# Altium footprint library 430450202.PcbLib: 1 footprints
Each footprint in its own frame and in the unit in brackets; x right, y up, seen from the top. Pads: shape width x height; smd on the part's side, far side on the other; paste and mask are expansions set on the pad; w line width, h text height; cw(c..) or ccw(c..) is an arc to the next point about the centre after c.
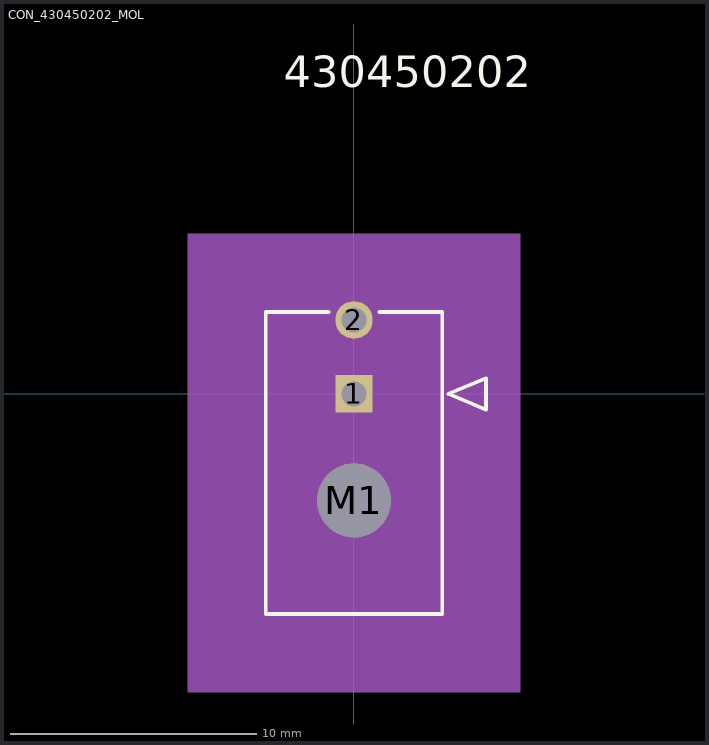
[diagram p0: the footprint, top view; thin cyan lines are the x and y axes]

## CON_430450202_MOL [mm]
pads (3):
  rect 1.52x1.52 hole 1.02 mask+0.076: 1(0,0)
  round 1.52 hole 1.02 mask+0.076: 2(0,3)
  round 3 hole 3 unplated mask+0.076: M1(0,-4.32)
Top Overlay:
  lines w0.152: -1.032,3.32 -3.575,3.32 -3.575,-8.92 3.575,-8.92 3.575,3.32 1.032,3.32 ; 3.829,0 5.353,0.635 5.353,-0.635 3.829,0
  text "430450202" at -2.857,12.44 h1.27
Mechanical 3:
  text "PTH_DRILL_SIZE:_1.02_MM,_TOLERANCE:_+0.05/-0.05" at -14.922,-15.5 h1.27
  text "NPTH_DRILL_SIZE:_3.0_MM,_TOLERANCE:_+0.05/-0.05" at -14.922,-18.04 h1.27
Mechanical 5:
  region: -6.75,6.495 6.75,6.495 6.75,-12.095 -6.75,-12.095
Mechanical 10:
  text "PTH_DRILL_SIZE:_1.02_MM,_TOLERANCE:_+0.05/-0.05" at -14.922,-15.5 h1.27
  text "NPTH_DRILL_SIZE:_3.0_MM,_TOLERANCE:_+0.05/-0.05" at -14.922,-18.04 h1.27
Mechanical 13:
  lines w0.127: -3.575,-8.92 3.575,-8.92 3.575,3.32 -3.575,3.32 -3.575,-8.92 ; 3.829,0 5.353,0.635 5.353,-0.635 3.829,0
  text "430450202" at -2.857,12.44 h1.27
Mechanical 15:
  region: 4.845,4.59 -4.845,4.59 -4.845,-10.19 4.845,-10.19
  lines w0.127: -4.845,-10.19 -4.845,4.59 4.845,4.59 4.845,-10.19 -4.845,-10.19
3D body: height 0.25, standoff 0, extent 0,0 0.254,0.254
3D body "430450202.stp": height 8.78, standoff -3.17, extent -3.575,-8.92 3.575,3.32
